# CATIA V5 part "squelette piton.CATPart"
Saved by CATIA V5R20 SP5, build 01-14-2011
Part number: squelette piton
Publications: "Point.3"
Bounding box of the stored display mesh (mm): x 0 to 20, y 200 to 200, z 180 to 200
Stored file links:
  F:\projet\yyang_IAO\squelette piton.CATPart
  F:\projet\yyang_IAO\iao.CATProduct
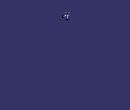
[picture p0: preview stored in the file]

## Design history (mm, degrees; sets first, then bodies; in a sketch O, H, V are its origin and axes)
Set1
  Plane1: linked copy from another document
  Point1: linked copy from another document
Body1 (main body)
  Plane2: type Offset, RefPlane Plane1, Offset 0
  Point2: (0, 0, 0), relative to Point1
  Line1: type PtDir, RefPoint Point1, Direction (1, 0, 0), Start 0, End 20
  Line2: type PtDir, RefPoint Point1, Direction (0, 0, 1), Start 0, End 20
